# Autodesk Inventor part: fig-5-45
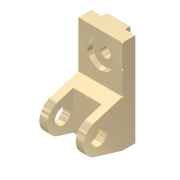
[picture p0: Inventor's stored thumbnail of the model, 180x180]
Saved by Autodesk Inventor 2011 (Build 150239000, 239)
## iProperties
Shininess: 65.0
Angle Display Precision: 2
Document Length Units: 11269
Document Angle Units: 11279
Document Time Units: 11290
Document Mass Units: 11283
Document Length Units Precision: 3
Document Angle Units Precision: 2
Created: 2001-11
Part Number: fig-5-45
Document SubType Name: Modeling
Designer: Renu Muthoo
Density: 1 g/cm^3
Density: 0.0
Volumn: 0.0
Area: 0.0
PropertySet Name: Model Information
Control State: 0
Master: False
Checked Out: False
Author: Renu Muthoo
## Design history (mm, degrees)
node "Sketch1"
sketch "Sketch2"
  geometry: L1 (33.257, 104.664)-(33.257, -75.336); L2 (33.257, -75.336)-(8.257, -75.336); L3 (8.257, -75.336)-(-45.451, -59.045); L4 (-45.451, -1.628)-(8.257, 14.664); L5 (8.257, 14.664)-(8.257, 104.664); L6 (8.257, 104.664)-(33.257, 104.664); C1 r 15 at (-36.743, -30.336); A1 r 30 centre (-36.743, -30.336) between (-45.451, -1.628) and (-45.451, -59.045)
  constraints: 12 end point, 2 centre point, 2 equal length, 2 parallel, 2 point on circle, 2 tangent, 1 coincident, 1 perpendicular, 1 vertical
  dimensions: "d0" = 180 distance of L1.start L1.end; "d1" = 30 radius of A1; "d2" = 25 distance of L5.end L1.start; "d3" = 45 distance from line of L2 A1.centre; "d4" = 70 distance from line of L1 A1.centre; "d5" = 30 diameter of C1
extrude "Extrusion1" new body sketch "Sketch2" distance "d6" = 85; taper "d7" = 0 deg
workplane "Work Plane1"
sketch "Sketch3"
  geometry: L1 (15, 62.364)-(70, 62.364); L2 (70, 62.364)-(70, -52.386); L3 (70, -52.386)-(15, -52.386); L4 (15, -52.386)-(15, 62.364); L5 (0, -45)-(0, -28.708) reference
  constraints: 8 end point, 2 parallel, 1 horizontal, 1 perpendicular
  dimensions: "d8" = 55 distance of L1.start L1.end; "d9" = 15 distance between parallel lines of L5 L4
extrude "Extrusion2" cut sketch "Sketch3" distance "d10" = 50; taper "d11" = 0 deg
sketch "Sketch4"
  geometry: L1 (0, 25)-(85, 25) reference; L2 (0, 0)-(0, 25) reference; L3 (20, 25)-(65, 25); L4 (65, 25)-(65, 35); L5 (65, 35)-(20, 35); L6 (20, 35)-(20, 25)
  constraints: 8 end point, 2 parallel, 1 horizontal, 1 perpendicular, 1 point on line
  dimensions: "d12" = 45 distance of L4.end L5.end; "d13" = 10 distance of L3.end L4.end; "d14" = 20 distance between parallel lines of L2 L6
extrude "Extrusion3" join sketch "Sketch4" stored distance "d15" = 50; taper "d16" = 0 deg
sketch "Sketch5"
  geometry: L1 (85, 0)-(85, 90) reference; L2 (0, 90)-(85, 90) reference; 1 further point
  dimensions: "d17" = 42 distance from line of L2 point (42.5, 48); "d18" = 42.5 distance from line of L1 point (42.5, 48)
hole "Hole1" sketch "Sketch5" at (42.5, 48) diameter "d19" = 20; stored, may be unused: countersink angle "d23" = 82 deg, drill point angle "d25" = 118 deg; dims "d20" = 6, "d21" = 50, "d22" = 10, "d24" = 8
workpoint "Work Point1"
workpoint "Work Point2"
workpoint "Work Point3"
workpoint "Work Point4"
workpoint "Work Point5"
body "Solid1"
